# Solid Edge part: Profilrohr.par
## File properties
Username: bmolnar
Dokumentum tartalom típus: 0
Author: bmolnar
Last saved by: bmolnar
Revision: 79
Sűrűség: 0,000 kg/m^3
Pontosság: 0,990
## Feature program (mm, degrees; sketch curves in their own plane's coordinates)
base feature "unnamed BaseFeature 1"
thread "unnamed Thread 1"
thread "Menet_2"  ThreadDepth = 6 mm
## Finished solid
Body 1: solid body, 153 faces, 364 edges, 236 vertices.
  Faces by surface: plane 74, cylinder 65, cone 10, torus 4
  Edges by curve: line 220, circle 140, curve on surface 2, spline 2
Bounding box of the edges (mm; curved faces can reach further): 46.000 x 51.000 x 44.500, from (-23, -24, 0) to (23, 27, 44.5).
Cylindrical faces by radius (mm): R0.3 x24, R0.8 x2, R2.9 x8, R4.283 x4, R4.4 x16, R16 x1, R16.85 x2, R17.05 x2, R17.9 x2, R30 x4
Conical faces (half-angle, radius in mm at the cone's reference point): 21 deg R16.325 x2, 45 deg R4.783 x2, 45 deg R17.1 x2, 45 deg R17.15 x2, 45 deg R17.2 x2
Toroidal faces (ring radius, tube radius in mm): R17.7 r0.2 x4
Planar faces by outward normal: +x 6, +y 9, +z 8, -x 6, -y 5, -z 8, oblique 32
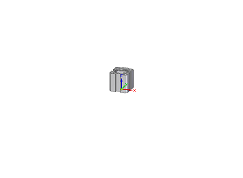
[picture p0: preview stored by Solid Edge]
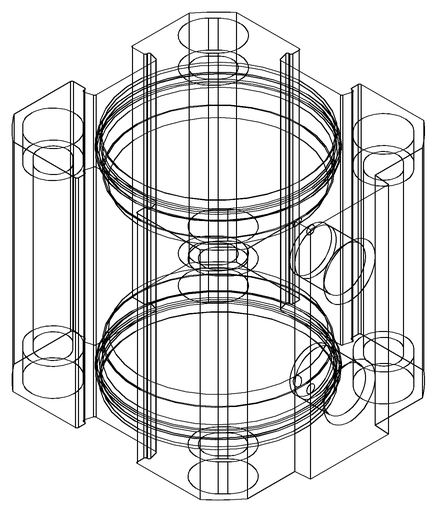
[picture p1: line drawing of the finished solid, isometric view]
